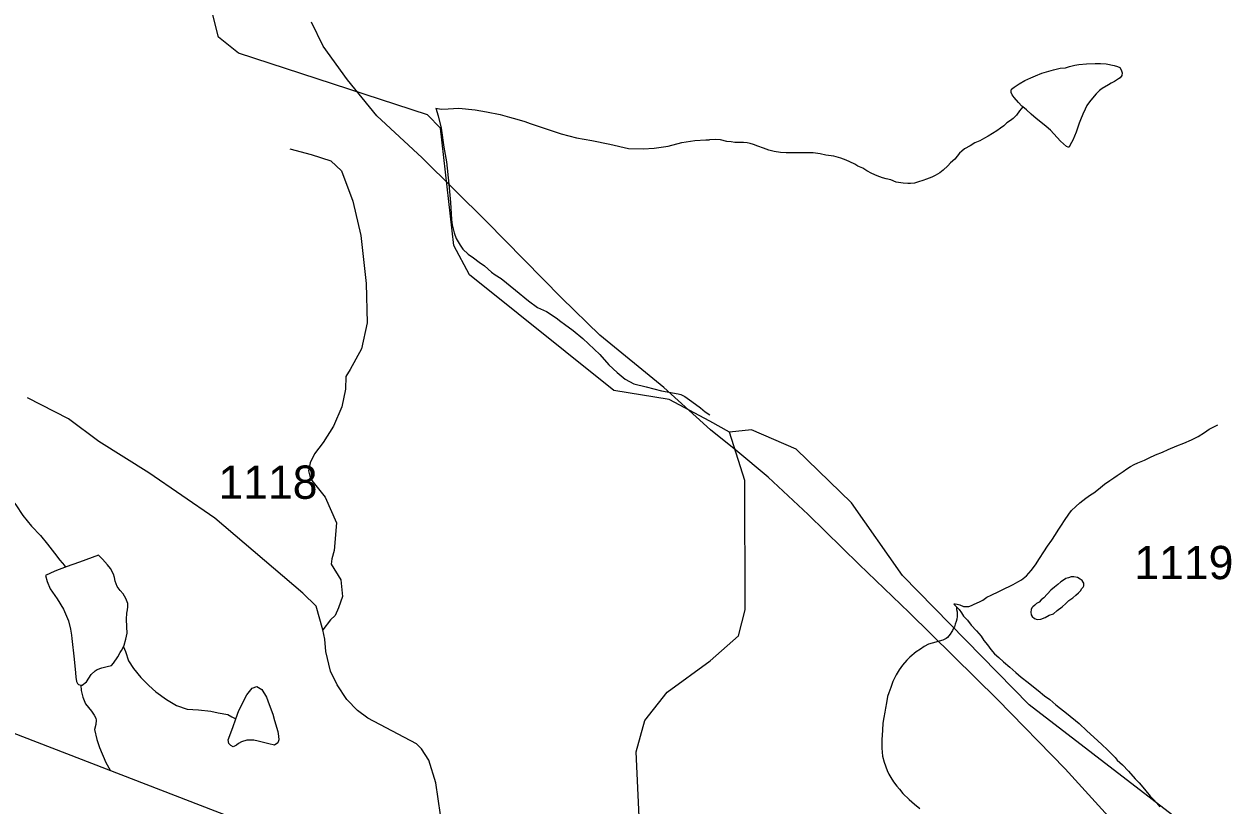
# Model space of a CAD drawing. Extents: x 2001466 to 2224147, y 644118 to 847247.
# Drawn here: x 2034669 to 2039151, y 663505 to 666438 of the extents above; entities that cross this region are included whole.
import ezdxf

# ---------------------------------------------------------------- set-up
doc = ezdxf.new("R2010")
doc.units = 0
for name, color, linetype in [('Exist Boundary Political CountyLine', 7, 'Continuous'), ('Exist Hydrographic Misc Water Feature', 7, 'Continuous'), ('Exist Railroad Mainline', 7, 'Continuous'), ('Exist Road Non-System Type 51', 7, 'Continuous'), ('Exist Road Secondary Type 51 Attributed', 7, 'Continuous'), ('Exist Road Secondary Type 51 Number Label', 7, 'Continuous')]:
    doc.layers.add(name, color=color, linetype=linetype)

msp = doc.modelspace()

# ---------------------------------------------------------------- linework, layer by layer
at = {"layer": 'Exist Boundary Political CountyLine'}
msp.add_lwpolyline([(2025347, 667357.1), (2026293.9, 666990.5), (2073692.9, 648709.4), (2076162.7, 647794.5), (2078580.1, 646988.2), (2083338.8, 645254.9), (2086621.1, 644117.9)], dxfattribs=at)
at = {"layer": 'Exist Hydrographic Misc Water Feature'}
for p, q in [((2037319.4, 664905.3), (2037245.6, 664946.2)), ((2038162.5, 664260.6), (2038164.6, 664256.6))]:
    msp.add_line(p, q, dxfattribs=at)
for points in [[(2037245.6, 664946.2), (2037092.4, 665027.9), (2036884.5, 665061.8), (2036342.5, 665496), (2036284.5, 665605.4), (2036234.4, 666046.1), (2036184.4, 666096.4), (2035475.5, 666327.3), (2035400.5, 666387.8), (2035358.5, 666552.7), (2035383.5, 666827.8), (2035158.5, 667176.9), (2035025.5, 667320.7), (2034950.4, 667492.8), (2034924.6, 667726.3), (2034849.5, 667803.3), (2034758.5, 668061.1)], [(2038421.1, 666126.9), (2038417.2, 666128.9), (2038405.1, 666142.8), (2038389.1, 666160.8), (2038381.1, 666170.8), (2038377, 666180.7), (2038377, 666186.7), (2038379.1, 666192.8), (2038389.1, 666200.8), (2038407, 666212.8), (2038428.9, 666224.8), (2038450.9, 666234.9), (2038468.9, 666242.9), (2038492.9, 666253), (2038536.8, 666265), (2038560.8, 666271.1), (2038580.9, 666273.1), (2038596.8, 666277.2), (2038616.7, 666283.2), (2038630.9, 666285.2), (2038660.8, 666287.3), (2038692.8, 666289.4), (2038712.7, 666289.4), (2038734.8, 666287.4), (2038764.8, 666281.5), (2038776.9, 666277.5), (2038784.9, 666273.5), (2038790.8, 666265.5), (2038794.7, 666253.5), (2038792.9, 666243.5), (2038786.9, 666235.5), (2038781, 666231.5), (2038765, 666221.5), (2038752.9, 666215.5), (2038742.8, 666209.4), (2038718.9, 666195.4), (2038709, 666187.4), (2038697.1, 666175.4), (2038683, 666159.4), (2038671.1, 666145.3), (2038661, 666131.3), (2038655.1, 666117.3), (2038647.1, 666099.3), (2038637.2, 666077.2), (2038633.1, 666065.2), (2038629.2, 666053.3), (2038621.3, 666031.2), (2038609.4, 666001.2), (2038599.5, 665983.2), (2038595.4, 665975.2), (2038591.3, 665975.2), (2038585.4, 665977.2), (2038563.2, 665997.1), (2038525.3, 666039.1), (2038509.3, 666053), (2038489.2, 666069), (2038471.2, 666083), (2038453.1, 666098.9), (2038435.3, 666114.9), (2038421.1, 666126.9)], [(2036216, 666121.1), (2036236.5, 666117.4), (2036262.3, 666119.4), (2036302.5, 666121), (2036364.4, 666115.6), (2036406.5, 666107.4), (2036458.4, 666097.3), (2036492.4, 666087.6), (2036520.5, 666079.6), (2036550.6, 666071.7), (2036570.5, 666063.9), (2036634.5, 666042.1), (2036686.8, 666025.4), (2036744.6, 666010.3), (2036802.6, 666000.1), (2036870.5, 665986.5), (2036940.6, 665970.3), (2036994.8, 665968.3), (2037036.6, 665970.8), (2037088.5, 665978.7), (2037140.6, 665992.4), (2037189, 665999.6), (2037230.6, 666002.9), (2037244.7, 666002.6)], [(2036216, 666121.1), (2036224.6, 666093), (2036236.5, 666046.8), (2036246.7, 665975.3), (2036257, 665919.3), (2036265, 665835.5), (2036271.1, 665767.3), (2036275.2, 665703.2), (2036277.3, 665683.5), (2036285.3, 665653), (2036293.3, 665631.5), (2036307.2, 665607.4), (2036317.5, 665591.6), (2036337.4, 665573.2), (2036357.5, 665559.6), (2036379.4, 665543.6), (2036399.5, 665529.2), (2036425.3, 665505.8), (2036439.5, 665495.6), (2036461.4, 665481.3), (2036515.6, 665437.5), (2036563.8, 665398), (2036597.6, 665373.5), (2036631.8, 665358.1), (2036667.7, 665334.3), (2036685.8, 665320), (2036699.7, 665309.9), (2036731.7, 665286.3), (2036768, 665256), (2036832, 665196.5), (2036866, 665158), (2036898, 665128.7), (2036927.9, 665104.3), (2036960.1, 665086.4), (2037006.1, 665074.8), (2037064.1, 665060.5), (2037126, 665048.7), (2037136.1, 665046.8), (2037152.1, 665039.1), (2037178.1, 665020.5), (2037210.3, 664996.9), (2037228.1, 664980.9), (2037246, 664969.9)], [(2038421.1, 666126.9), (2038409.2, 666110.9), (2038397.1, 666094.8), (2038385.2, 666082.8), (2038375.4, 666074.8), (2038361.2, 666066.7), (2038349.4, 666054.7), (2038337.3, 666046.7), (2038323.3, 666036.6), (2038307.3, 666026.6), (2038291.3, 666016.6), (2038277.4, 666008.6), (2038259.3, 665998.6), (2038241.5, 665990.6), (2038223.4, 665980.5), (2038201.5, 665968.5), (2038191.5, 665960.5), (2038183.5, 665952.4), (2038165.6, 665930.4), (2038149.6, 665916.3), (2038139.6, 665904.3), (2038121.7, 665888.3), (2038109.6, 665878.3), (2038091.6, 665868.3), (2038079.7, 665862.3), (2038059.6, 665854.2), (2038045.7, 665850.2), (2038029.7, 665844.2), (2038013.7, 665840.2), (2037999.7, 665838.1), (2037989.7, 665838.1), (2037971.9, 665840.1), (2037945.8, 665844), (2037925.7, 665851.9), (2037907.7, 665855.9), (2037893.7, 665859.9), (2037873.6, 665867.8), (2037853.7, 665875.8), (2037835.7, 665885.8), (2037819.7, 665895.8), (2037801.7, 665903.7), (2037789.8, 665911.7), (2037771.7, 665919.7), (2037757.6, 665925.7), (2037737.5, 665933.6), (2037711.6, 665941.5), (2037681.5, 665945.5), (2037659.6, 665949.4), (2037633.5, 665953.4), (2037609.5, 665953.3), (2037589.6, 665953.3), (2037565.6, 665953.3), (2037547.6, 665953.3), (2037531.6, 665953.2), (2037511.5, 665955.1), (2037487.5, 665959.1), (2037467.6, 665963.1), (2037447.5, 665971.1), (2037425.6, 665979), (2037409.6, 665985), (2037397.5, 665989), (2037385.6, 665991), (2037371.5, 665992.9), (2037355.5, 665992.9), (2037339.5, 665992.8), (2037325.5, 665994.8), (2037309.5, 665996.8), (2037285.5, 666002.8), (2037266.3, 666003.5), (2037244.7, 666002.6)], [(2038162.5, 664260.6), (2038166.7, 664260.6), (2038174.6, 664258.7), (2038184.7, 664256.7), (2038198.6, 664250.7), (2038210.5, 664250.8), (2038218.5, 664250.8), (2038228.6, 664254.8), (2038238.6, 664258.8), (2038246.6, 664262.8), (2038260.6, 664268.8), (2038270.4, 664274.8), (2038286.4, 664284.9), (2038302.4, 664292.9), (2038330.5, 664307), (2038356.5, 664319), (2038370.3, 664325), (2038384.4, 664333.1), (2038402.5, 664343.1), (2038416.4, 664351.2), (2038434.4, 664365.2), (2038452.3, 664385.2), (2038468.3, 664407.2), (2038484.3, 664431.2), (2038500.1, 664455.3), (2038514.2, 664477.3), (2038530.2, 664499.4), (2038543.9, 664521.4), (2038554, 664537.4), (2038566.1, 664555.3), (2038577.8, 664573.4), (2038593.8, 664597.4), (2038603.8, 664611.4), (2038619.8, 664625.5), (2038635.8, 664639.5), (2038657.8, 664657.6), (2038675.8, 664669.6), (2038687.7, 664677.6), (2038705.7, 664691.6), (2038727.7, 664709.6), (2038747.6, 664723.7), (2038763.6, 664733.7), (2038775.7, 664741.7), (2038797.6, 664757.8), (2038811.5, 664767.8), (2038825.5, 664775.9), (2038839.4, 664783.9), (2038853.6, 664789.9), (2038877.6, 664799.9), (2038895.4, 664808), (2038919.4, 664820), (2038945.4, 664830.1), (2038967.4, 664840.1), (2038999.4, 664854.2), (2039025.4, 664864.2), (2039055.3, 664876.3), (2039079.3, 664888.3), (2039103.3, 664904.3), (2039121.2, 664916.4), (2039153.2, 664932.4)], [(2037246.6, 664047), (2037353.4, 664140.1), (2037378.4, 664238), (2037377.4, 664723.6), (2037319.4, 664905.3)], [(2039146.4, 663342.5), (2038445.3, 663881.7), (2037969.4, 664367.1), (2037777.5, 664640), (2037569.3, 664841.1), (2037402.4, 664913.4), (2037319.4, 664905.3)], [(2034363.5, 664858.6), (2034385.1, 664842.6), (2034421, 664804.1), (2034439.2, 664790.6), (2034457.1, 664780.4), (2034497.2, 664768.1), (2034545.2, 664756.5), (2034565.3, 664744.7), (2034587.3, 664704.8), (2034611.3, 664666.6), (2034639.3, 664632.4), (2034665.6, 664592.5), (2034697.6, 664552.5), (2034731.6, 664516.5), (2034757.5, 664484.8), (2034783.5, 664450.6), (2034803.8, 664424.8), (2034821.4, 664404.8), (2034828, 664398.9)], [(2035043.1, 664099.2), (2035046.2, 664105.7), (2035052.1, 664127.8), (2035057.2, 664149.8), (2035056, 664173.6), (2035054, 664203.2), (2035056, 664225.3), (2035057.9, 664237.5), (2035059.1, 664249), (2035059.7, 664261.3), (2035051.7, 664281.1), (2035041.9, 664297.8), (2035030, 664311.1), (2035019.7, 664325.3), (2035011.7, 664345.2), (2035009.7, 664359.1), (2035005.6, 664371.5), (2034993.7, 664393.1), (2034983.6, 664407.2), (2034963.9, 664428.1), (2034949.6, 664443.1), (2034877.6, 664416.8), (2034828, 664398.9)], [(2034828, 664398.9), (2034785.5, 664383.3), (2034749.9, 664366.9), (2034755.8, 664344.6), (2034767.9, 664317.3), (2034794, 664279), (2034817.9, 664240.7), (2034836, 664197), (2034844.2, 664164.8), (2034848.1, 664143.4), (2034849.1, 664130.3), (2034858.3, 664053), (2034862.4, 664001.2), (2034864.3, 663985.6), (2034866.5, 663969.2), (2034870.4, 663960.9), (2034874.3, 663957.5), (2034882.7, 663955.6)], [(2038526.3, 664311.3), (2038500.5, 664283.3), (2038490.4, 664275.3), (2038482.4, 664267.3), (2038472.6, 664261.3), (2038466.4, 664255.2), (2038458.4, 664249.2), (2038454.5, 664245.2), (2038452.7, 664239.2), (2038450.6, 664229.2), (2038452.7, 664219.2), (2038456.6, 664213.2), (2038464.6, 664205.2), (2038474.6, 664201.3), (2038488.6, 664203.3), (2038504.6, 664209.4), (2038520.6, 664217.4), (2038536.6, 664223.4), (2038550.7, 664235.4), (2038568.6, 664249.4), (2038582.5, 664261.5), (2038594.4, 664273.5), (2038608.5, 664283.5), (2038620.4, 664293.5), (2038630.3, 664301.5), (2038638.3, 664309.5), (2038642.4, 664317.5), (2038648.3, 664323.6), (2038650.4, 664327.6), (2038650.4, 664333.6), (2038650.4, 664337.6), (2038648.3, 664341.5), (2038644.4, 664347.5), (2038636.4, 664353.5), (2038626.4, 664359.5), (2038612.4, 664361.5), (2038602.4, 664361.5), (2038592.3, 664357.5), (2038582.3, 664355.4), (2038574.3, 664349.4), (2038564.5, 664343.4), (2038552.4, 664333.4), (2038540.5, 664323.3), (2038526.3, 664311.3)], [(2038164.6, 664256.6), (2038172.5, 664248.7), (2038172.6, 664238.7), (2038174.6, 664230.7), (2038174.6, 664222.7), (2038174.6, 664212.7), (2038172.8, 664202.7), (2038170.8, 664194.7), (2038166.7, 664184.7), (2038164.8, 664174.7), (2038160.7, 664168.7), (2038156.8, 664160.7), (2038154.8, 664156.7), (2038148.8, 664146.7), (2038142.9, 664140.7), (2038138.8, 664134.6), (2038132.8, 664130.6), (2038120.9, 664124.6), (2038106.8, 664120.6), (2038094.9, 664116.6), (2038066.8, 664108.5), (2038050.8, 664100.5), (2038036.9, 664090.4), (2038021.1, 664080.4), (2037997.1, 664060.4), (2037985, 664048.4), (2037969, 664030.4), (2037957.1, 664012.3), (2037945.2, 663994.3), (2037933.1, 663968.3), (2037925.3, 663946.3), (2037917.3, 663926.3), (2037913.2, 663912.3), (2037909.3, 663888.3), (2037905.4, 663868.3), (2037903.4, 663854.3), (2037899.3, 663834.3), (2037895.6, 663812.3), (2037893.5, 663786.3), (2037891.7, 663750.3), (2037891.7, 663718.3), (2037893.7, 663688.3), (2037899.7, 663666.3), (2037911.8, 663634.4), (2037917.9, 663620.4), (2037925.9, 663608.3), (2037935.8, 663592.3), (2037947.9, 663576.4), (2037957.9, 663564.4), (2037970, 663548.4), (2037994, 663526.4), (2038013.9, 663508.5), (2038034, 663492.6)], [(2038164.6, 664256.6), (2038172.5, 664248.7), (2038182.6, 664238.7), (2038190.6, 664226.7), (2038198.6, 664214.7), (2038212.8, 664198.8), (2038226.7, 664180.8), (2038246.8, 664158.8), (2038264.7, 664138.9), (2038274.9, 664122.9), (2038288.9, 664106.9), (2038301, 664089), (2038314.9, 664073), (2038330.9, 664059), (2038348.9, 664043), (2038372.9, 664023.1), (2038395.1, 664003.1), (2038415, 663985.3), (2038441, 663965.2), (2038461.1, 663949.3), (2038479.1, 663935.4), (2038503.1, 663915.3), (2038523.2, 663901.4), (2038545.2, 663881.5), (2038563.2, 663867.5), (2038585.2, 663849.6), (2038633.3, 663811.6), (2038661.4, 663783.7), (2038687.3, 663759.7), (2038717.4, 663731.8), (2038739.6, 663711.9), (2038767.5, 663683.9), (2038775.7, 663673.9), (2038795.5, 663656), (2038817.7, 663632), (2038843.7, 663604.1), (2038857.7, 663588.1), (2038877.8, 663564.1), (2038899.7, 663538.2), (2038911.8, 663526.2), (2038923.9, 663512.2), (2038935.8, 663498.3)], [(2034882.7, 663955.6), (2034888.5, 663955.5), (2034904.5, 663967.5), (2034922.3, 663995), (2034936.5, 664009.5), (2034944.3, 664013.4), (2034962.3, 664019.6), (2034982.2, 664025), (2034998.2, 664029.6), (2035006.2, 664037.6), (2035022.4, 664061.1), (2035030.2, 664077.3), (2035036.1, 664085.4), (2035043.1, 664099.2)], [(2035043.1, 664099.2), (2035050.3, 664081.8), (2035062.2, 664047.1), (2035080.2, 664017.3), (2035108.3, 663983.9), (2035138.4, 663953.8), (2035164.5, 663929.5), (2035204.5, 663901.5), (2035242.4, 663879.4), (2035282.6, 663865.6), (2035324.4, 663862.2), (2035370.6, 663858), (2035398.4, 663851.7), (2035434.5, 663844.4), (2035450.5, 663835.8), (2035465.7, 663829)], [(2036935.9, 662886), (2036994.4, 663163.1), (2036968.3, 663705), (2037001.3, 663822.4), (2037085.4, 663929), (2037246.6, 664047)], [(2034882.7, 663955.6), (2034884.4, 663935.2), (2034890.5, 663909.6), (2034900.6, 663885.6), (2034922.7, 663857.2), (2034932.6, 663843.1), (2034938.7, 663831.5), (2034940.6, 663823.3), (2034938.7, 663807.7), (2034934.8, 663788.9), (2034942.8, 663751), (2034952.9, 663721.2), (2034976.9, 663665), (2034992.5, 663635.6)], [(2035465.7, 663829), (2035476.6, 663860), (2035506.5, 663918.4), (2035526.4, 663944.2), (2035544.4, 663950.4), (2035562.3, 663938.6), (2035580.3, 663910.4), (2035590.4, 663882.2), (2035604.3, 663846.6), (2035610.5, 663822.8), (2035622.6, 663780.7), (2035624.8, 663764.2), (2035626.7, 663750.3), (2035622.8, 663738.8), (2035610.7, 663730.1), (2035588.5, 663734.7), (2035548.5, 663744.5), (2035532.8, 663748.1), (2035506.7, 663748.6), (2035486.6, 663742.5), (2035474.5, 663736.1), (2035467.1, 663729.7), (2035454.8, 663724.2), (2035446.8, 663728.5), (2035438.8, 663736), (2035436.8, 663750.1), (2035454.4, 663796.4), (2035465.7, 663829)]]:
    msp.add_lwpolyline(points, dxfattribs=at)
at = {"layer": 'Exist Railroad Mainline'}
msp.add_lwpolyline([(2038929.2, 663256.5), (2038580.1, 663640.8), (2038325.4, 663901.5), (2037994.2, 664227.9), (2037806.9, 664407.9), (2037614.7, 664595.8), (2037464.5, 664735.8), (2037342.6, 664837.7), (2037247.4, 664913.8), (2037072.5, 665072.3), (2036832.7, 665269), (2036688.5, 665408.7), (2036406, 665696), (2036164.8, 665935), (2035994.6, 666093), (2035884.4, 666228.3), (2035793.7, 666353.5), (2035749, 666444)], dxfattribs=at)
at = {"layer": 'Exist Road Non-System Type 51'}
msp.add_lwpolyline([(2035668.5, 665969), (2035748.3, 665948), (2035822, 665923.1), (2035861.6, 665886.7), (2035904.1, 665772.2), (2035934.7, 665643.8), (2035954.4, 665463.6), (2035958.6, 665315.5), (2035937.4, 665217.7), (2035894.4, 665140.4), (2035878.1, 665114.5), (2035877.5, 665066.5), (2035862.8, 665000.6), (2035831.9, 664927), (2035793, 664865.6), (2035760.6, 664823.9), (2035744.1, 664790.2), (2035737.9, 664760.1), (2035745.5, 664730.2), (2035800.7, 664661.5), (2035843.5, 664565), (2035834.2, 664461), (2035825.8, 664429.1), (2035823.6, 664409.2), (2035859, 664351.1), (2035865.4, 664288.5), (2035850.7, 664245.7), (2035837.9, 664216.9), (2035820.8, 664200.8), (2035791.9, 664162.3)], dxfattribs=at)
at = {"layer": 'Exist Road Secondary Type 51 Attributed'}
msp.add_lwpolyline([(2036253.4, 663149.3), (2036234, 663468.9), (2036216.4, 663588.5), (2036190.3, 663673.9), (2036163, 663715.6), (2036144.1, 663735.4), (2035960.9, 663831.2), (2035922.4, 663860.1), (2035881.8, 663901.3), (2035845.4, 663955.8), (2035820.8, 664007.2), (2035802.6, 664081), (2035799.4, 664128.1), (2035791.9, 664162.3), (2035766.3, 664252.2), (2035717.1, 664300.3), (2035386.6, 664581.7), (2035138.6, 664752.9), (2034950.3, 664870.5), (2034836.9, 664954.7), (2034682.5, 665034.2)], dxfattribs=at)

# ---------------------------------------------------------------- texts
at = {"layer": 'Exist Road Secondary Type 51 Number Label'}
for s, p in [('1118', (2035399.9, 664654.7)), ('1119', (2038840.2, 664353.1))]:
    msp.add_text(s, height=125, dxfattribs=at).set_placement(p)

doc.saveas('drawing.dxf')
